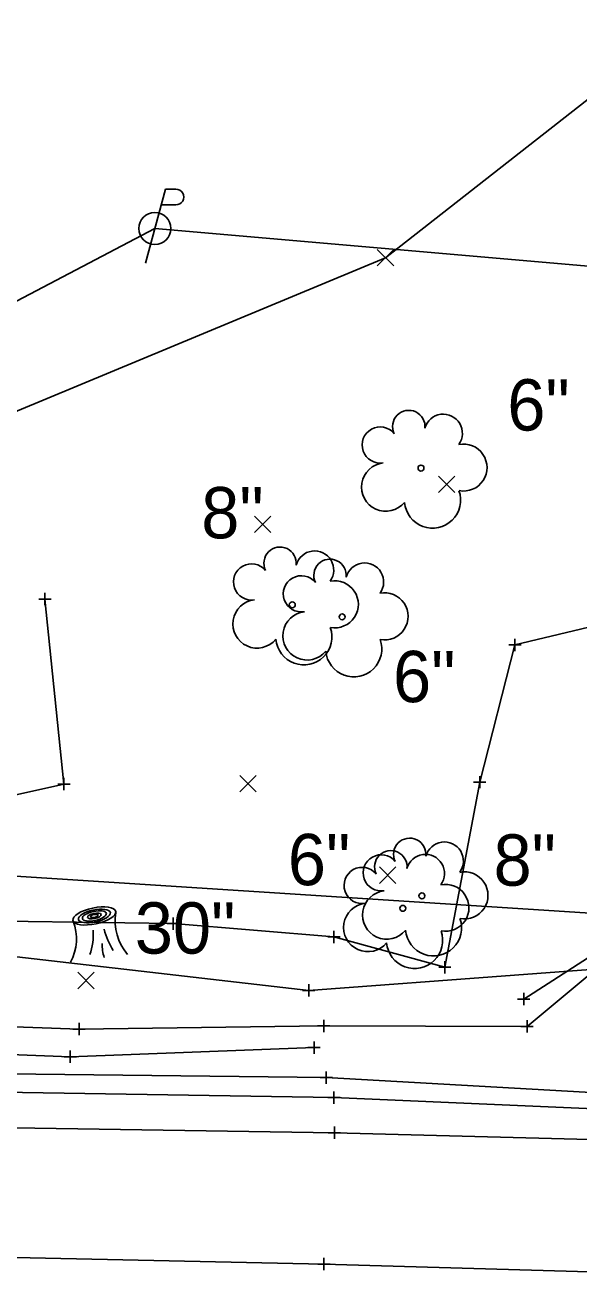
# Model space of a CAD drawing. Extents: x 2005176 to 2005823, y 572472 to 572942.
# Drawn here: x 2005452.2 to 2005497.2, y 572608.1 to 572710.8 of the extents above; entities that cross this region are included whole.
import ezdxf

# ---------------------------------------------------------------- set-up
doc = ezdxf.new("R2010")
doc.units = 0
for name, color, linetype in [('GE_X_Alignment_1000_Bearings', 7, 'Continuous'), ('GE_X_Alignment_1000_Cardinal_Points', 7, 'Continuous'), ('GE_X_Alignment_100_Bearings', 7, 'Continuous'), ('GE_X_Alignment_100_Cardinal_Points', 7, 'Continuous'), ('GE_X_Alignment_100_Distances', 7, 'Continuous'), ('GE_X_Alignment_100_Stations', 7, 'Continuous'), ('GE_X_Alignment_500_Bearings', 7, 'Continuous'), ('GE_X_Alignment_500_Cardinal_Points', 7, 'Continuous'), ('GE_X_Alignment_500_Distances', 7, 'Continuous'), ('SC_Scratch10', 7, 'Continuous'), ('SC_Scratch8', 7, 'Continuous'), ('SC_Scratch9', 7, 'Continuous'), ('SV_P_Mon_Cells_Set', 7, 'Continuous'), ('SV_X_Random_Point', 7, 'Continuous'), ('SV_X_Shot_Marker', 7, 'Continuous'), ('SV_X_Terrain_Boundary', 7, 'Continuous'), ('UT_X_Overhead_Electric', 7, 'Continuous'), ('VG_X_Text', 7, 'Continuous')]:
    doc.layers.add(name, color=color, linetype=linetype)

msp = doc.modelspace()

# ---------------------------------------------------------------- linework, layer by layer
at = {"layer": 'GE_X_Alignment_1000_Bearings'}
msp.add_lwpolyline([(2005377.36, 572646.47), (2005740.51, 572623.1)], dxfattribs=at)
at = {"layer": 'GE_X_Alignment_1000_Cardinal_Points'}
msp.add_lwpolyline([(2005589.36, 572669.58), (2005577.83, 572653.68), (2005542.16, 572637.38), (2005475.27, 572632.41), (2005412.5, 572639.63), (2005455.37, 572649.17), (2005453.82, 572664.21)], dxfattribs=at)
at = {"layer": 'GE_X_Alignment_100_Bearings'}
msp.add_lwpolyline([(2005220.7, 572626.42), (2005272.19, 572624.71), (2005322.24, 572623.5), (2005370.59, 572622.7), (2005425.14, 572621.65), (2005477.36, 572620.84), (2005525.07, 572619.6), (2005576.7, 572617.86), (2005628.14, 572615.99), (2005678.39, 572614.09), (2005728.23, 572612.03), (2005777.04, 572611.02), (2005819.95, 572609.99)], dxfattribs=at)
at = {"layer": 'GE_X_Alignment_100_Cardinal_Points'}
msp.add_lwpolyline([(2005220.5, 572615.99), (2005272.51, 572614.37), (2005322.2, 572613.2), (2005370.62, 572612.29), (2005424.94, 572611.27), (2005476.5, 572610.17), (2005524.32, 572608.79), (2005576.49, 572607.4), (2005627.69, 572605.77), (2005677.11, 572603.68), (2005728.03, 572601.92), (2005776.18, 572600.5), (2005820.14, 572599.28)], dxfattribs=at)
at = {"layer": 'GE_X_Alignment_100_Distances'}
msp.add_lwpolyline([(2005220.68, 572626.38), (2005272.19, 572624.71), (2005322.24, 572623.5), (2005370.59, 572622.7), (2005425.14, 572621.65), (2005477.36, 572620.84), (2005525.07, 572619.6), (2005576.7, 572617.86), (2005628.14, 572615.99), (2005678.39, 572614.09), (2005728.23, 572612.03), (2005777.04, 572611.02), (2005820.02, 572609.9)], dxfattribs=at)
at = {"layer": 'GE_X_Alignment_100_Stations'}
msp.add_lwpolyline([(2005222.43, 572636.47), (2005271.73, 572636.06), (2005321.63, 572634.11), (2005368.05, 572633.72), (2005426.44, 572630.35), (2005456.6, 572629.27), (2005476.49, 572629.52), (2005493.02, 572629.48), (2005502.46, 572637.33)], dxfattribs=at)
at = {"layer": 'GE_X_Alignment_500_Bearings'}
for points in [[(2005542.84, 572700.3), (2005523.82, 572678.95), (2005515.82, 572663.82), (2005510.49, 572650.26), (2005510.36, 572641.52), (2005504.71, 572639.4), (2005492.74, 572631.71)], [(2005221.46, 572633.88), (2005271.77, 572632.29), (2005321.33, 572630.21), (2005368.11, 572629.36), (2005426.58, 572628.14), (2005455.88, 572627.02), (2005475.7, 572627.77)]]:
    msp.add_lwpolyline(points, dxfattribs=at)
at = {"layer": 'GE_X_Alignment_500_Cardinal_Points'}
msp.add_lwpolyline([(2005223.7, 572649.48), (2005272.16, 572646.31), (2005321.29, 572642.61), (2005368.45, 572643.7), (2005424.94, 572638.4), (2005464.26, 572637.84), (2005477.31, 572636.75), (2005486.33, 572634.29), (2005489.17, 572649.33), (2005492.03, 572660.48), (2005500.98, 572662.63), (2005517.14, 572685.76), (2005532.69, 572703.48)], dxfattribs=at)
at = {"layer": 'GE_X_Alignment_500_Distances'}
msp.add_lwpolyline([(2005220.4, 572616.04), (2005272.51, 572614.37), (2005322.2, 572613.2), (2005370.62, 572612.29), (2005424.94, 572611.27), (2005476.5, 572610.17), (2005524.32, 572608.79), (2005576.49, 572607.4), (2005627.69, 572605.77), (2005677.11, 572603.68), (2005728.03, 572601.92), (2005776.18, 572600.5), (2005820.14, 572599.26)], dxfattribs=at)
at = {"layer": 'SC_Scratch10'}
msp.add_lwpolyline([(2005220.88, 572629.15), (2005272.14, 572627.64), (2005321.83, 572626.68), (2005370.65, 572626), (2005424.7, 572625.92), (2005476.69, 572625.33), (2005525.49, 572622.56), (2005576.48, 572620.99), (2005628.3, 572618.68), (2005678.32, 572615.98), (2005728.35, 572614.83)], dxfattribs=at)
at = {"layer": 'SC_Scratch8'}
msp.add_lwpolyline([(2005220.9, 572628.72), (2005272.16, 572627.13), (2005321.83, 572625.74), (2005370.81, 572625), (2005424.98, 572624.56), (2005477.31, 572623.7), (2005525.21, 572621.63), (2005576.56, 572620.01), (2005628.24, 572617.89), (2005678.25, 572615.23), (2005728.27, 572613.25), (2005777.12, 572612.24), (2005820.02, 572611.5)], dxfattribs=at)
at = {"layer": 'SC_Scratch9'}
for p, q in [((2005463.62, 572697.51), (2005462.01, 572691.51)), ((2005463.62, 572697.51), (2005464.47, 572697.51)), ((2005463.28, 572696.24), (2005464.47, 572696.24))]:
    msp.add_line(p, q, dxfattribs=at)
msp.add_circle((2005462.76, 572694.31), 1.3, dxfattribs=at)
msp.add_arc((2005464.48, 572696.87), 0.638, 268.8767, 91.1233, dxfattribs=at)
at = {"layer": 'SV_P_Mon_Cells_Set'}
for p, q in [((2005453.32, 572664.21), (2005454.32, 572664.21)), ((2005453.82, 572664.71), (2005453.82, 572663.71)), ((2005453.82, 572664.21), (2005453.82, 572664.21)), ((2005491.53, 572660.48), (2005492.53, 572660.48)), ((2005492.03, 572660.98), (2005492.03, 572659.98)), ((2005492.03, 572660.48), (2005492.03, 572660.48)), ((2005489.17, 572649.83), (2005489.17, 572648.83)), ((2005454.87, 572649.17), (2005455.87, 572649.17)), ((2005455.37, 572649.67), (2005455.37, 572648.67)), ((2005455.37, 572649.17), (2005455.37, 572649.17)), ((2005488.67, 572649.33), (2005489.67, 572649.33)), ((2005489.17, 572649.33), (2005489.17, 572649.33)), ((2005463.76, 572637.84), (2005464.76, 572637.84)), ((2005464.26, 572638.34), (2005464.26, 572637.34)), ((2005464.26, 572637.84), (2005464.26, 572637.84)), ((2005476.81, 572636.75), (2005477.81, 572636.75)), ((2005477.31, 572637.25), (2005477.31, 572636.25)), ((2005477.31, 572636.75), (2005477.31, 572636.75)), ((2005485.83, 572634.29), (2005486.83, 572634.29)), ((2005486.33, 572634.79), (2005486.33, 572633.79)), ((2005486.33, 572634.29), (2005486.33, 572634.29)), ((2005474.77, 572632.41), (2005475.77, 572632.41)), ((2005475.27, 572632.91), (2005475.27, 572631.91)), ((2005475.27, 572632.41), (2005475.27, 572632.41)), ((2005492.24, 572631.71), (2005493.24, 572631.71)), ((2005492.74, 572632.21), (2005492.74, 572631.21)), ((2005492.74, 572631.71), (2005492.74, 572631.71)), ((2005456.1, 572629.27), (2005457.1, 572629.27)), ((2005456.6, 572629.77), (2005456.6, 572628.77)), ((2005456.6, 572629.27), (2005456.6, 572629.27)), ((2005475.99, 572629.52), (2005476.99, 572629.52)), ((2005476.49, 572630.02), (2005476.49, 572629.02)), ((2005476.49, 572629.52), (2005476.49, 572629.52)), ((2005492.52, 572629.48), (2005493.52, 572629.48)), ((2005493.02, 572629.98), (2005493.02, 572628.98)), ((2005493.02, 572629.48), (2005493.02, 572629.48)), ((2005475.7, 572628.27), (2005475.7, 572627.27)), ((2005455.88, 572627.52), (2005455.88, 572626.52)), ((2005475.2, 572627.77), (2005476.2, 572627.77)), ((2005475.7, 572627.77), (2005475.7, 572627.77)), ((2005455.38, 572627.02), (2005456.38, 572627.02)), ((2005455.88, 572627.02), (2005455.88, 572627.02)), ((2005476.19, 572625.33), (2005477.19, 572625.33)), ((2005476.69, 572625.83), (2005476.69, 572624.83)), ((2005476.69, 572625.33), (2005476.69, 572625.33)), ((2005477.31, 572624.2), (2005477.31, 572623.2)), ((2005476.81, 572623.7), (2005477.81, 572623.7)), ((2005477.31, 572623.7), (2005477.31, 572623.7)), ((2005477.36, 572621.34), (2005477.36, 572620.34)), ((2005477.36, 572621.34), (2005477.36, 572620.34)), ((2005476.86, 572620.84), (2005477.86, 572620.84)), ((2005476.86, 572620.84), (2005477.86, 572620.84)), ((2005477.36, 572620.84), (2005477.36, 572620.84)), ((2005477.36, 572620.84), (2005477.36, 572620.84)), ((2005476.5, 572610.67), (2005476.5, 572609.67)), ((2005476.5, 572610.67), (2005476.5, 572609.67)), ((2005476, 572610.17), (2005477, 572610.17)), ((2005476, 572610.17), (2005477, 572610.17)), ((2005476.5, 572610.17), (2005476.5, 572610.17)), ((2005476.5, 572610.17), (2005476.5, 572610.17))]:
    msp.add_line(p, q, dxfattribs=at)
at = {"layer": 'SV_X_Random_Point'}
for p, q in [((2005480.84, 572691.27), (2005482.18, 572692.61)), ((2005480.84, 572692.61), (2005482.18, 572691.27)), ((2005485.81, 572672.86), (2005487.14, 572674.19)), ((2005485.81, 572674.19), (2005487.14, 572672.86)), ((2005470.86, 572669.61), (2005472.19, 572670.95)), ((2005470.86, 572670.95), (2005472.19, 572669.61)), ((2005469.67, 572648.54), (2005471, 572649.88)), ((2005469.67, 572649.88), (2005471, 572648.54)), ((2005481.03, 572641.11), (2005482.36, 572642.45)), ((2005481.03, 572642.45), (2005482.36, 572641.11)), ((2005456.5, 572632.55), (2005457.83, 572633.89)), ((2005456.5, 572633.89), (2005457.83, 572632.55))]:
    msp.add_line(p, q, dxfattribs=at)
at = {"layer": 'SV_X_Shot_Marker'}
msp.add_line((2005458.22, 572636.95), (2005458.22, 572636.95), dxfattribs=at)
for centre in [(2005484.39, 572674.85), (2005473.93, 572663.74), (2005477.98, 572662.76), (2005484.47, 572640.09), (2005482.92, 572639.08)]:
    msp.add_circle(centre, 0.24, dxfattribs=at)
for centre, radius, start, end in [((2005483.4, 572678.22), 1.32, 354.0047, 205.9741), ((2005486.21, 572677.68), 1.55, 323.83, 165.0376), ((2005481.08, 572676.72), 1.47, 39.0625, 279.5412), ((2005487.85, 572674.89), 1.91, 259.1453, 101.4596), ((2005481.53, 572673.31), 1.97, 96.1722, 320.5737), ((2005485.33, 572672.25), 2.28, 184.9476, 19.4572), ((2005472.94, 572667.11), 1.32, 354.0047, 205.9741), ((2005475.75, 572666.57), 1.55, 323.83, 165.0376), ((2005477, 572666.13), 1.32, 354.0047, 205.9741), ((2005470.62, 572665.6), 1.47, 39.0625, 279.5412), ((2005479.81, 572665.59), 1.55, 323.83, 165.0376), ((2005474.67, 572664.63), 1.47, 39.0625, 279.5412), ((2005477.39, 572663.78), 1.91, 259.1453, 101.4596), ((2005471.07, 572662.19), 1.97, 96.1722, 320.5737), ((2005481.44, 572662.8), 1.91, 259.1453, 101.4596), ((2005475.13, 572661.22), 1.97, 96.1722, 320.5737), ((2005474.87, 572661.14), 2.28, 184.9476, 19.4572), ((2005478.93, 572660.16), 2.28, 184.9476, 19.4572), ((2005483.48, 572643.46), 1.32, 354.0047, 205.9741), ((2005481.94, 572642.45), 1.32, 354.0047, 205.9741), ((2005486.29, 572642.92), 1.55, 323.83, 165.0376), ((2005481.16, 572641.96), 1.47, 39.0625, 279.5412), ((2005484.75, 572641.91), 1.55, 323.83, 165.0376), ((2005479.61, 572640.94), 1.47, 39.0625, 279.5412), ((2005487.93, 572640.13), 1.91, 259.1453, 101.4596), ((2005481.61, 572638.54), 1.97, 96.1722, 320.5737), ((2005486.38, 572639.12), 1.91, 259.1453, 101.4596), ((2005480.07, 572637.53), 1.97, 96.1722, 320.5737), ((2005463.82, 572638.09), 4.29, 171.4106, 219.9194), ((2005452.39, 572636.61), 4, 331.5338, 20.9269), ((2005464.73, 572639.01), 6.32, 194.9653, 212.1216), ((2005485.41, 572637.49), 2.28, 184.9476, 19.4572), ((2005452.7, 572636.98), 5.05, 340.7938, 3.5481), ((2005483.87, 572636.47), 2.28, 184.9476, 19.4572), ((2005462.12, 572636.15), 3.64, 178.7926, 197.1224)]:
    msp.add_arc(centre, radius, start, end, dxfattribs=at)
for major_axis in [(1.74, 0.37), (1.3, 0.28), (0.976, 0.211), (0.549, 0.119), (0.309, 0.067)]:
    msp.add_ellipse((2005457.84, 572638.46), major_axis=major_axis, ratio=0.36865, dxfattribs=at)
at = {"layer": 'SV_X_Terrain_Boundary'}
msp.add_lwpolyline([(2005682.42, 572646.03), (2005631.48, 572658.58), (2005562.59, 572707.41), (2005552.72, 572710.82), (2005513.74, 572704), (2005498.99, 572705.6), (2005481.51, 572691.94), (2005424.05, 572668.06)], dxfattribs=at)
at = {"layer": 'UT_X_Overhead_Electric'}
for p, q in [((2005235.79, 572575.46), (2005462.76, 572694.31)), ((2005462.76, 572694.31), (2005730.63, 572670.98))]:
    msp.add_line(p, q, dxfattribs=at)

# ---------------------------------------------------------------- texts
at = {"layer": 'VG_X_Text'}
for s, p in [('6"', (2005491.41, 572677.9)), ('8"', (2005466.53, 572669.14)), ('6"', (2005482.12, 572655.83)), ('6"', (2005473.57, 572640.96)), ('8"', (2005490.29, 572640.92)), ('30"', (2005461.13, 572635.4))]:
    msp.add_text(s, height=4.167, dxfattribs=at).set_placement(p)

doc.saveas('drawing.dxf')
